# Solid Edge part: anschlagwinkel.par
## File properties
Title: Anschlagwinkel
Author: ra-tv
Template: Normal.par
Last saved by: ra-11
Revision: 9
Application: Solid Edge
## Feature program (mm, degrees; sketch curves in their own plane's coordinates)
sketch for "unnamed Protrusion 1" plane through (0, 0, 0) normal (0, 0, 1) x-axis (1, 0, 0)
  line (-41.0667, -28.2667) -> (33.9333, -28.2667)
  line (33.9333, -28.2667) -> (33.9333, -3.2667)
  line (33.9333, -3.2667) -> (-41.0667, -3.2667)
  line (-41.0667, -3.2667) -> (-41.0667, -28.2667)
extrude "unnamed Protrusion 1" add finite 4 along -normal
sketch for "unnamed Protrusion 2" plane through (-3.5667, -28.2667, -2) normal (0, -1, 0) x-axis (1, 0, 0)
  line (-37.5, -2) -> (-37.5, -23)
  line (-37.5, -23) -> (37.5, -23)
  line (37.5, -23) -> (37.5, -2)
extrude "unnamed Protrusion 2" add finite 4 along -normal
sketch for "unnamed Hole 1" plane through (-3.5667, -15.7667, 0) normal (0, 0, 1) x-axis (1, 0, 0)
  hole centre (0, 0) bore radius 3.4
hole "unnamed Hole 1" through
sketch for "unnamed Hole 2" plane through (-3.5667, -15.7667, 0) normal (0, 0, 1) x-axis (1, 0, 0)
  hole centre (25, 0) bore radius 1.65
hole "unnamed Hole 2" through
sketch for "unnamed Hole 3" plane through (-3.5667, -15.7667, 0) normal (0, 0, 1) x-axis (1, 0, 0)
  hole centre (-25, 0) bore radius 1.65
hole "unnamed Hole 3" through
sketch for "unnamed Hole 4" plane through (-3.5667, -15.7667, 0) normal (0, 0, 1) x-axis (1, 0, 0)
  hole centre (30.5, 5.5) bore radius 2
hole "unnamed Hole 4" through
sketch for "unnamed Hole 5" plane through (-3.5667, -15.7667, 0) normal (0, 0, 1) x-axis (1, 0, 0)
  hole centre (-30.5, 5.5) bore radius 2
hole "unnamed Hole 5" through
sketch for "unnamed Hole 6" plane through (-3.5667, -15.7667, 0) normal (0, 0, 1) x-axis (1, 0, 0)
  hole centre (19.5, -5.5) bore radius 2
hole "unnamed Hole 6" through
sketch for "unnamed Hole 7" plane through (-3.5667, -15.7667, 0) normal (0, 0, 1) x-axis (1, 0, 0)
  hole centre (-19.5, -5.5) bore radius 2
hole "unnamed Hole 7" through
fillet "unnamed Round 1"
fillet "unnamed Round 2"
pattern "unnamed Pattern 1" of "unnamed Hole 4", "unnamed Hole 5"
pattern "unnamed Pattern 2" of "unnamed Hole 6", "unnamed Hole 7"
